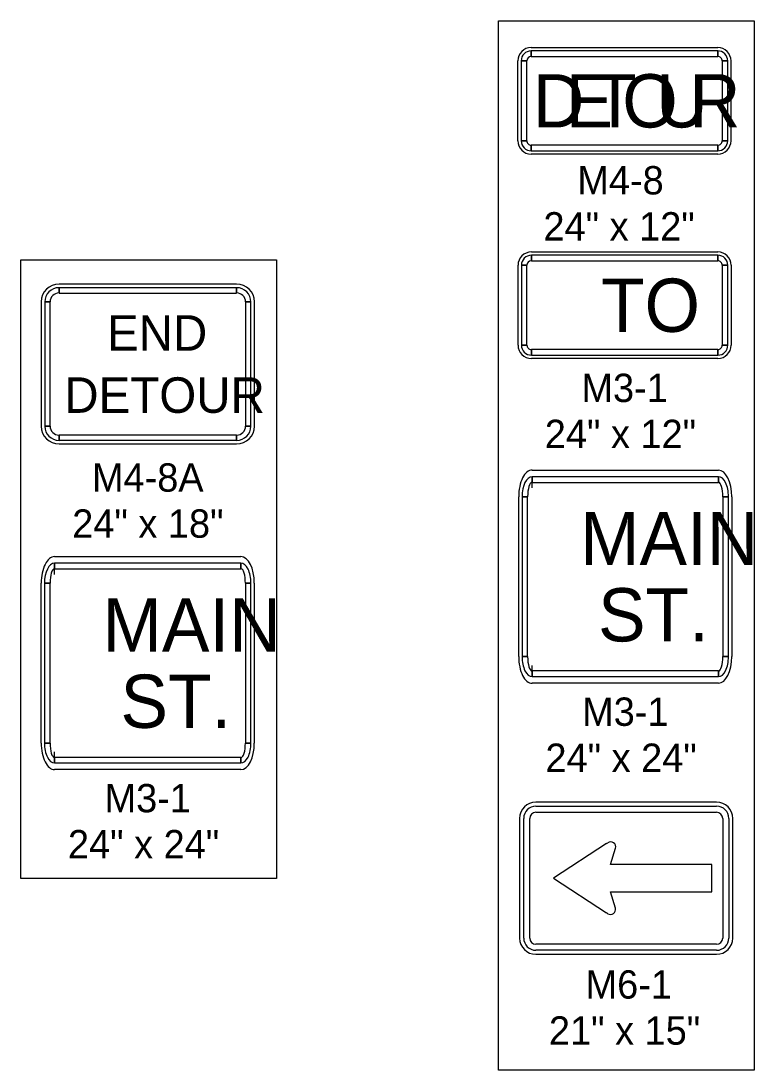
# Model space of a CAD drawing. Extents: x 10133 to 81668, y 6132 to 11018.
# Drawn here: x 12098.8 to 12305.6, y 6725.4 to 7021.5 of the extents above; entities that cross this region are included whole.
import ezdxf

# ---------------------------------------------------------------- set-up
doc = ezdxf.new("R2010")
doc.units = 0
for name, color, linetype in [('dsnTextFinalPlan', 7, 'Continuous'), ('Level 10', 7, 'Continuous'), ('Level 5', 7, 'Continuous')]:
    doc.layers.add(name, color=color, linetype=linetype)

msp = doc.modelspace()

# ---------------------------------------------------------------- linework, layer by layer
at = {"layer": 'dsnTextFinalPlan'}
for points in [[(12233.53, 7021.45), (12305.59, 7021.45), (12305.59, 6725.36), (12233.53, 6725.36)], [(12098.8, 6954.02), (12170.87, 6954.02), (12170.87, 6779.42), (12098.8, 6779.42)]]:
    msp.add_lwpolyline(points, close=True, dxfattribs=at)
at = {"layer": 'Level 10'}
for p, q in [((12242.73, 7013.94), (12295.35, 7013.94)), ((12242.73, 7011.44), (12242.73, 7013)), ((12295.35, 7013), (12295.35, 7011.44)), ((12238.97, 6987.64), (12238.97, 7010.19)), ((12239.91, 7010.19), (12241.48, 7010.19)), ((12296.6, 7010.19), (12298.16, 7010.19)), ((12299.1, 7010.19), (12299.1, 6987.64)), ((12241.48, 6987.64), (12239.91, 6987.64)), ((12242.73, 6984.82), (12242.73, 6986.39)), ((12295.35, 6986.39), (12295.35, 6984.82)), ((12298.16, 6987.64), (12296.6, 6987.64)), ((12295.35, 6983.88), (12242.73, 6983.88)), ((12242.78, 6956.26), (12295.39, 6956.26)), ((12242.78, 6953.75), (12242.78, 6955.32)), ((12295.39, 6955.32), (12295.39, 6953.75)), ((12239.02, 6929.95), (12239.02, 6952.5)), ((12239.96, 6952.5), (12241.53, 6952.5)), ((12296.64, 6952.5), (12298.21, 6952.5)), ((12299.15, 6952.5), (12299.15, 6929.95)), ((12159.64, 6947.18), (12109.53, 6947.18)), ((12109.53, 6944.67), (12109.53, 6946.18)), ((12159.64, 6946.18), (12109.53, 6946.18)), ((12109.53, 6946.18), (12109.53, 6944.67)), ((12109.53, 6944.67), (12159.64, 6944.67)), ((12159.64, 6944.67), (12159.64, 6946.18)), ((12159.64, 6946.18), (12159.64, 6944.67)), ((12104.52, 6942.17), (12104.52, 6907.09)), ((12105.52, 6942.17), (12105.52, 6907.09)), ((12107.03, 6942.17), (12105.52, 6942.17)), ((12105.52, 6942.17), (12107.03, 6942.17)), ((12107.03, 6907.09), (12107.03, 6942.17)), ((12162.15, 6942.17), (12163.65, 6942.17)), ((12162.15, 6942.17), (12162.15, 6907.09)), ((12163.65, 6942.17), (12162.15, 6942.17)), ((12163.65, 6907.09), (12163.65, 6942.17)), ((12164.65, 6907.09), (12164.65, 6942.17)), ((12241.53, 6929.95), (12239.96, 6929.95)), ((12242.78, 6927.13), (12242.78, 6928.7)), ((12295.39, 6928.7), (12295.39, 6927.13)), ((12298.21, 6929.95), (12296.64, 6929.95)), ((12295.39, 6926.19), (12242.78, 6926.19)), ((12105.52, 6907.09), (12107.03, 6907.09)), ((12107.03, 6907.09), (12105.52, 6907.09)), ((12162.15, 6907.09), (12163.65, 6907.09)), ((12163.65, 6907.09), (12162.15, 6907.09)), ((12159.64, 6904.59), (12109.53, 6904.59)), ((12109.53, 6904.59), (12109.53, 6903.09)), ((12109.53, 6903.09), (12109.53, 6904.59)), ((12109.53, 6903.09), (12159.64, 6903.09)), ((12109.53, 6902.08), (12159.64, 6902.08)), ((12159.64, 6904.59), (12159.64, 6903.09)), ((12159.64, 6903.09), (12159.64, 6904.59)), ((12242.97, 6894.67), (12295.58, 6894.67)), ((12242.97, 6889.66), (12242.97, 6892.8)), ((12295.58, 6892.8), (12295.58, 6891.23)), ((12239.21, 6842.06), (12239.21, 6887.16)), ((12240.15, 6887.16), (12241.72, 6887.16)), ((12296.84, 6887.16), (12298.4, 6887.16)), ((12299.34, 6887.16), (12299.34, 6842.06)), ((12108.24, 6870.27), (12160.86, 6870.27)), ((12108.24, 6865.26), (12108.24, 6868.39)), ((12160.86, 6868.39), (12160.86, 6866.83)), ((12104.49, 6817.66), (12104.49, 6862.76)), ((12105.43, 6862.76), (12106.99, 6862.76)), ((12162.11, 6862.76), (12163.68, 6862.76)), ((12164.62, 6862.76), (12164.62, 6817.66)), ((12241.72, 6842.06), (12240.15, 6842.06)), ((12298.4, 6842.06), (12296.84, 6842.06)), ((12242.97, 6836.43), (12242.97, 6839.56)), ((12295.58, 6837.99), (12295.58, 6836.43)), ((12295.58, 6834.55), (12242.97, 6834.55)), ((12106.99, 6817.66), (12105.43, 6817.66)), ((12163.68, 6817.66), (12162.11, 6817.66)), ((12108.24, 6812.02), (12108.24, 6815.15)), ((12160.86, 6813.59), (12160.86, 6812.02)), ((12160.86, 6810.14), (12108.24, 6810.14)), ((12295.02, 6800.97), (12244.06, 6800.97)), ((12244.07, 6799.82), (12295.03, 6799.82)), ((12239.47, 6796.38), (12239.47, 6762.6)), ((12240.63, 6762.6), (12240.63, 6796.38)), ((12242.35, 6762.6), (12242.35, 6796.38)), ((12244.07, 6798.1), (12295.03, 6798.1)), ((12296.75, 6796.38), (12296.75, 6762.6)), ((12298.47, 6796.38), (12298.47, 6762.6)), ((12299.6, 6762.6), (12299.6, 6796.38)), ((12295.03, 6760.88), (12244.07, 6760.88)), ((12244.06, 6758.02), (12295.02, 6758.02)), ((12295.03, 6759.16), (12244.07, 6759.16))]:
    msp.add_line(p, q, dxfattribs=at)
for points in [[(12295.35, 7013), (12242.73, 7013), (12242.73, 7011.44), (12295.35, 7011.44), (12295.35, 7013)], [(12239.91, 7010.19), (12239.91, 6987.64), (12241.48, 6987.64), (12241.48, 7010.19), (12239.91, 7010.19)], [(12298.16, 6987.64), (12298.16, 7010.19), (12296.6, 7010.19), (12296.6, 6987.64), (12298.16, 6987.64)], [(12242.73, 6984.82), (12295.35, 6984.82), (12295.35, 6986.39), (12242.73, 6986.39), (12242.73, 6984.82)], [(12295.39, 6955.32), (12242.78, 6955.32), (12242.78, 6953.75), (12295.39, 6953.75), (12295.39, 6955.32)], [(12239.96, 6952.5), (12239.96, 6929.95), (12241.53, 6929.95), (12241.53, 6952.5), (12239.96, 6952.5)], [(12298.21, 6929.95), (12298.21, 6952.5), (12296.64, 6952.5), (12296.64, 6929.95), (12298.21, 6929.95)], [(12242.78, 6927.13), (12295.39, 6927.13), (12295.39, 6928.7), (12242.78, 6928.7), (12242.78, 6927.13)], [(12295.58, 6892.8), (12242.97, 6892.8), (12242.97, 6891.23), (12295.58, 6891.23), (12295.58, 6892.8)], [(12240.15, 6887.16), (12240.15, 6842.06), (12241.72, 6842.06), (12241.72, 6887.16), (12240.15, 6887.16)], [(12298.4, 6842.06), (12298.4, 6887.16), (12296.84, 6887.16), (12296.84, 6842.06), (12298.4, 6842.06)], [(12160.86, 6868.39), (12108.24, 6868.39), (12108.24, 6866.83), (12160.86, 6866.83), (12160.86, 6868.39)], [(12105.43, 6862.76), (12105.43, 6817.66), (12106.99, 6817.66), (12106.99, 6862.76), (12105.43, 6862.76)], [(12163.68, 6817.66), (12163.68, 6862.76), (12162.11, 6862.76), (12162.11, 6817.66), (12163.68, 6817.66)], [(12242.97, 6836.43), (12295.58, 6836.43), (12295.58, 6837.99), (12242.97, 6837.99), (12242.97, 6836.43)], [(12108.24, 6812.02), (12160.86, 6812.02), (12160.86, 6813.59), (12108.24, 6813.59), (12108.24, 6812.02)]]:
    msp.add_lwpolyline(points, close=True, dxfattribs=at)
for points in [[(12264.02, 6789.31), (12249.03, 6779.49), (12264.02, 6769.7)], [(12266.49, 6771.03), (12265.12, 6775.61), (12293.65, 6775.61), (12293.65, 6783.37), (12265.12, 6783.37), (12266.51, 6787.94)]]:
    msp.add_lwpolyline(points, dxfattribs=at)
for centre, radius, start, end in [((12242.73, 7010.19), 3.76, 90, 180), ((12242.73, 7010.19), 2.82, 90.0002, 179.9998), ((12295.35, 7010.19), 3.76, 0, 90), ((12295.35, 7010.19), 2.82, 0, 90.0002), ((12242.73, 7010.19), 1.25, 90.0002, 179.9998), ((12295.35, 7010.19), 1.25, 0, 90.0002), ((12242.73, 6987.64), 3.76, 180, 270), ((12242.73, 6987.64), 2.82, 179.9998, 270.0001), ((12242.73, 6987.64), 1.25, 179.9998, 270.0001), ((12295.35, 6987.64), 2.82, 270.0001, 0.0003), ((12295.35, 6987.64), 1.25, 270.0001, 0.0003), ((12295.35, 6987.64), 3.76, 270, 359.9911), ((12242.78, 6952.5), 3.76, 90, 180), ((12242.78, 6952.5), 2.82, 90.0002, 179.9998), ((12295.39, 6952.5), 3.76, 0, 90), ((12295.39, 6952.5), 2.82, 0, 90.0002), ((12242.78, 6952.5), 1.25, 90.0002, 179.9998), ((12295.39, 6952.5), 1.25, 0, 90.0002), ((12109.53, 6942.17), 5.01, 90, 180), ((12159.64, 6942.17), 5.01, 0, 90), ((12109.53, 6942.17), 4.01, 90, 180), ((12109.53, 6942.17), 2.51, 90, 180), ((12159.64, 6942.17), 4.01, 0, 90), ((12159.64, 6942.17), 2.51, 0, 90), ((12242.78, 6929.95), 3.76, 180, 270), ((12242.78, 6929.95), 2.82, 179.9998, 270.0001), ((12242.78, 6929.95), 1.25, 179.9998, 270.0001), ((12295.39, 6929.95), 2.82, 270.0001, 0.0003), ((12295.39, 6929.95), 1.25, 270.0001, 0.0003), ((12295.39, 6929.95), 3.76, 270, 359.9911), ((12109.53, 6907.09), 5.01, 180, 270), ((12109.53, 6907.09), 4.01, 180, 270), ((12109.53, 6907.09), 2.51, 180, 270), ((12159.64, 6907.09), 2.51, 270, 0), ((12159.64, 6907.09), 4.01, 270, 360), ((12159.64, 6907.09), 5.01, 270, 0), ((12244.06, 6796.38), 4.58, 90, 180), ((12244.07, 6796.38), 3.44, 90, 180), ((12295.02, 6796.38), 4.58, 360, 90), ((12295.03, 6796.38), 3.44, 0, 90), ((12244.07, 6796.38), 1.72, 90, 180), ((12295.03, 6796.38), 1.72, 0, 90), ((12185.56, 6909.06), 143.16, 303.2286, 303.3891), ((12265.14, 6788.33), 1.43, 344.0309, 123.3891), ((12185.75, 6649.83), 143.16, 56.6896, 56.857), ((12265.14, 6770.65), 1.4, 236.6896, 15.9691), ((12244.06, 6762.6), 4.58, 180, 270), ((12244.07, 6762.6), 3.44, 180, 270), ((12244.07, 6762.6), 1.72, 180, 270), ((12295.02, 6762.6), 4.58, 270, 0), ((12295.03, 6762.6), 3.44, 270, 0), ((12295.03, 6762.6), 1.72, 270, 0)]:
    msp.add_arc(centre, radius, start, end, dxfattribs=at)
for centre, major_axis, ratio, start_param, end_param in [((12242.97, 6887.16), (0, 7.52), 0.5, 6.283185, 7.853982), ((12295.58, 6887.16), (0, 7.52), 0.5, 4.712389, 6.283185), ((12242.97, 6887.16), (0, 5.64), 0.5, 0.000004, 1.570794), ((12242.97, 6887.16), (0, 4.07), 0.307692, 0.000004, 1.570794), ((12295.58, 6887.16), (0, 5.64), 0.5, 4.712389, 6.283189), ((12295.58, 6887.16), (0, 4.07), 0.307692, 4.712389, 6.283189), ((12108.24, 6862.76), (0, 7.52), 0.5, 6.283185, 7.853982), ((12160.86, 6862.76), (0, 7.52), 0.5, 4.712389, 6.283185), ((12108.24, 6862.76), (0, 5.64), 0.5, 0.000004, 1.570794), ((12108.24, 6862.76), (0, 4.07), 0.307692, 0.000004, 1.570794), ((12160.86, 6862.76), (0, 5.64), 0.5, 4.712389, 6.283189), ((12160.86, 6862.76), (0, 4.07), 0.307692, 4.712389, 6.283189), ((12242.97, 6842.06), (0, 7.52), 0.5, 1.570796, 3.141593), ((12242.97, 6842.06), (0, 5.64), 0.5, 1.570794, 3.141594), ((12242.97, 6842.06), (0, 4.07), 0.307692, 1.570794, 3.141594), ((12295.58, 6842.06), (0, 5.64), 0.5, 3.141594, 4.712394), ((12295.58, 6842.06), (0, 4.07), 0.307692, 3.141594, 4.712394), ((12295.58, 6842.06), (0, 7.52), 0.5, 3.141593, 4.712234), ((12108.24, 6817.66), (0, 7.52), 0.5, 1.570796, 3.141593), ((12108.24, 6817.66), (0, 5.64), 0.5, 1.570794, 3.141594), ((12108.24, 6817.66), (0, 4.07), 0.307692, 1.570794, 3.141594), ((12160.86, 6817.66), (0, 5.64), 0.5, 3.141594, 4.712394), ((12160.86, 6817.66), (0, 4.07), 0.307692, 3.141594, 4.712394), ((12160.86, 6817.66), (0, 7.52), 0.5, 3.141593, 4.712234)]:
    msp.add_ellipse(centre, major_axis=major_axis, ratio=ratio, start_param=start_param, end_param=end_param, dxfattribs=at)

# ---------------------------------------------------------------- texts
for s, height, p in [('D', 15.03, (12243.22, 6991.4)), ('E', 15.03, (12252.46, 6991.4)), ('T', 15.03, (12260.24, 6991.4)), ('O', 15.03, (12268.44, 6991.4)), ('U', 15.03, (12278.03, 6991.4)), ('R', 15.03, (12287.27, 6991.4)), ('TO', 15.032, (12262.44, 6933.71)), ('END', 10.021, (12123.06, 6928.39)), ('DETOUR', 10.021, (12111.01, 6910.85)), ('MAIN', 15.032, (12256.54, 6867.86)), ('ST.', 15.032, (12261.59, 6846.33)), ('MAIN', 15.032, (12121.81, 6843.46)), ('ST.', 15.032, (12126.86, 6821.93))]:
    msp.add_text(s, height=height, dxfattribs=at).set_placement(p)
at = {"layer": 'Level 5'}
for s, p in [('M4-8', (12255.74, 6972.49)), ('24" x 12"', (12246.19, 6959.49)), ('M3-1', (12256.9, 6913.9)), ('24" x 12"', (12246.57, 6900.9)), ('M4-8A', (12118.81, 6888.6)), ('24" x 18"', (12113.25, 6875.6)), ('M3-1', (12257.1, 6822.5)), ('24" x 24"', (12246.76, 6809.5)), ('M3-1', (12122.37, 6798.1)), ('24" x 24"', (12112.04, 6785.1)), ('M6-1', (12258.07, 6745.51)), ('21" x 15"', (12247.73, 6732.51))]:
    msp.add_text(s, height=8, dxfattribs=at).set_placement(p)

doc.saveas('drawing.dxf')
